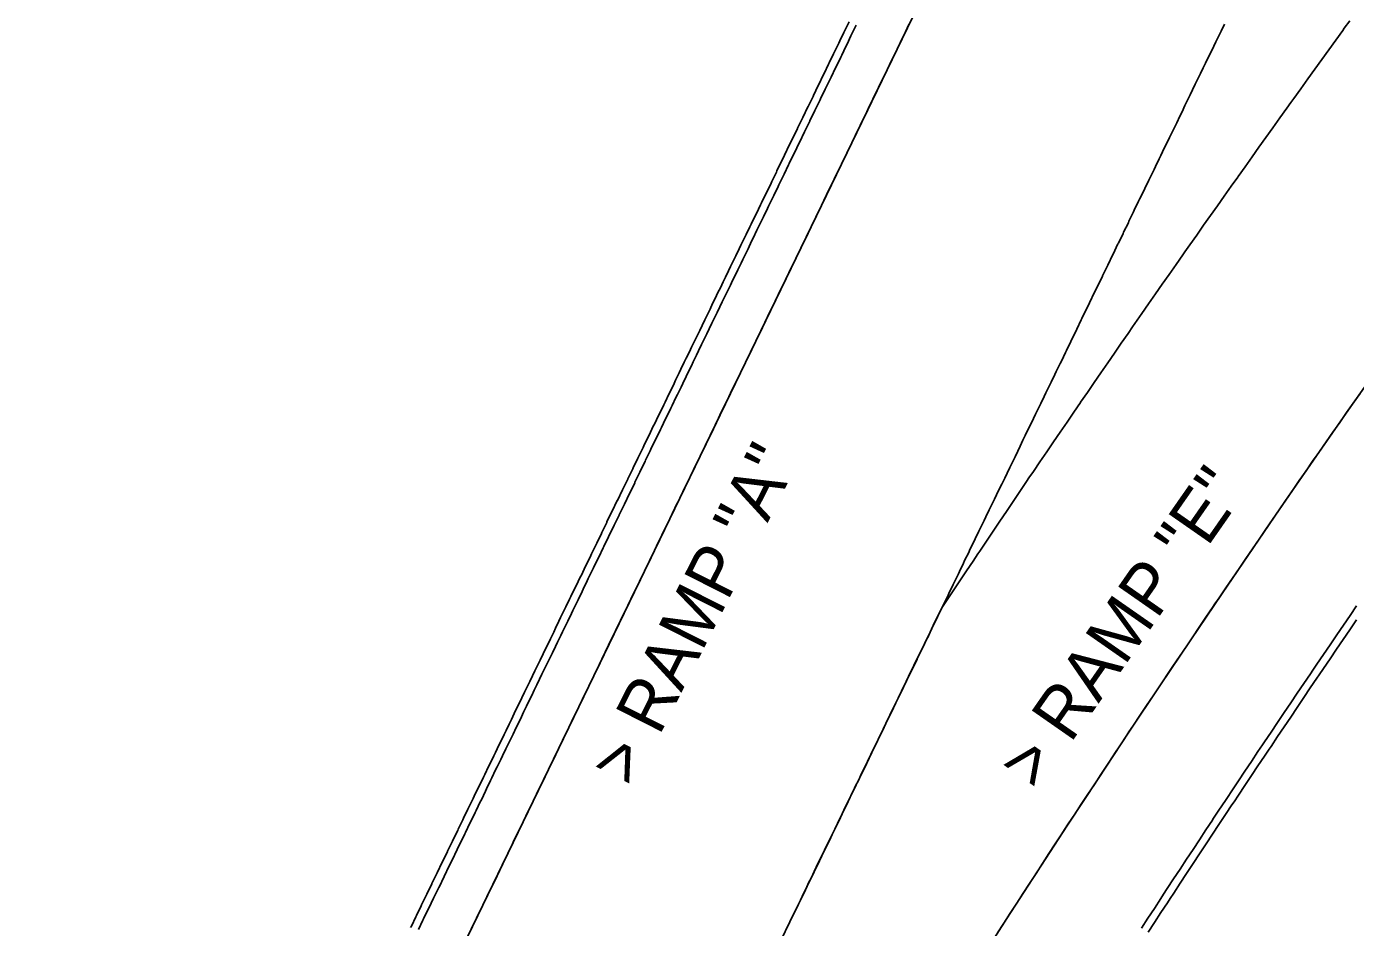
# Model space of a CAD drawing. Extents: x 2145147 to 2158018, y 137519 to 148068.
# Drawn here: x 2151102.2 to 2151214.6, y 141901.3 to 141977.5 of the extents above; entities that cross this region are included whole.
import ezdxf

# ---------------------------------------------------------------- set-up
doc = ezdxf.new("R2010")
doc.units = 0
for name, color, linetype in [('PR_Align_Ramp_A', 7, 'Continuous'), ('PR_Align_Ramp_A_Label', 7, 'Continuous'), ('PR_Align_Ramp_E', 7, 'Continuous'), ('PR_Align_Ramp_E_Label', 7, 'Continuous'), ('PR_Phasing_Pavement_1', 7, 'Continuous')]:
    doc.layers.add(name, color=color, linetype=linetype)

msp = doc.modelspace()

# ---------------------------------------------------------------- linework, layer by layer
at = {"layer": 'PR_Align_Ramp_A'}
msp.add_line((2151104.34, 141827.89), (2151311.03, 142254.91), dxfattribs=at)
at = {"layer": 'PR_Align_Ramp_E'}
msp.add_arc((2152388.44, 141125.03), 1432.39, 138.84043, 162.99163, dxfattribs=at)
at = {"layer": 'PR_Phasing_Pavement_1'}
for points in [[(2151134.68, 141901.28), (2151134.74, 141901.41), (2151135.12, 141902.21), (2151135.17, 141902.31), (2151135.57, 141903.13), (2151135.61, 141903.21), (2151136.02, 141904.06), (2151136.04, 141904.11), (2151136.47, 141904.98), (2151136.48, 141905.01), (2151136.92, 141905.91), (2151136.92, 141905.91), (2151137.35, 141906.81), (2151137.37, 141906.84), (2151137.79, 141907.71), (2151137.81, 141907.76), (2151138.22, 141908.61), (2151138.26, 141908.69), (2151138.66, 141909.51), (2151138.71, 141909.62), (2151139.1, 141910.41), (2151139.16, 141910.54), (2151139.53, 141911.31), (2151139.61, 141911.47), (2151139.97, 141912.21), (2151140.06, 141912.4), (2151140.4, 141913.11), (2151140.51, 141913.32), (2151140.84, 141914.01), (2151140.95, 141914.25), (2151141.27, 141914.91), (2151141.4, 141915.17), (2151141.71, 141915.81), (2151141.85, 141916.1), (2151142.14, 141916.71), (2151142.3, 141917.03), (2151142.58, 141917.61), (2151142.75, 141917.95), (2151143.02, 141918.51), (2151143.2, 141918.88), (2151143.45, 141919.41), (2151143.64, 141919.81), (2151143.89, 141920.31), (2151144.09, 141920.73), (2151144.32, 141921.21), (2151144.54, 141921.66), (2151144.76, 141922.11), (2151144.99, 141922.59), (2151145.19, 141923.01), (2151145.44, 141923.51), (2151145.63, 141923.91), (2151145.89, 141924.44), (2151146.06, 141924.81), (2151146.33, 141925.36), (2151146.5, 141925.71), (2151146.78, 141926.29), (2151146.94, 141926.61), (2151147.23, 141927.22), (2151147.37, 141927.51), (2151147.68, 141928.14), (2151147.81, 141928.41), (2151148.13, 141929.07), (2151148.24, 141929.31), (2151148.58, 141930), (2151148.68, 141930.21), (2151149.02, 141930.92), (2151149.12, 141931.11), (2151149.47, 141931.85), (2151149.55, 141932.01), (2151149.92, 141932.77), (2151149.99, 141932.91), (2151150.37, 141933.7), (2151150.42, 141933.81), (2151150.82, 141934.63), (2151150.86, 141934.71), (2151151.27, 141935.55), (2151151.29, 141935.61), (2151151.71, 141936.48), (2151151.73, 141936.51), (2151152.16, 141937.41), (2151152.17, 141937.41), (2151152.6, 141938.31), (2151152.61, 141938.33), (2151153.04, 141939.21), (2151153.06, 141939.26), (2151153.47, 141940.11), (2151153.51, 141940.19), (2151153.91, 141941.01), (2151153.96, 141941.11), (2151154.34, 141941.91), (2151154.4, 141942.04), (2151154.78, 141942.81), (2151154.85, 141942.96), (2151155.21, 141943.71), (2151155.3, 141943.89), (2151155.65, 141944.61), (2151155.75, 141944.82), (2151156.09, 141945.51), (2151156.2, 141945.74), (2151156.52, 141946.41), (2151156.65, 141946.67), (2151156.96, 141947.31), (2151157.1, 141947.6), (2151157.39, 141948.21), (2151157.54, 141948.52), (2151157.83, 141949.11), (2151157.99, 141949.45), (2151158.26, 141950.01), (2151158.44, 141950.38), (2151158.7, 141950.91), (2151158.89, 141951.3), (2151159.14, 141951.81), (2151159.34, 141952.23), (2151159.57, 141952.71), (2151159.79, 141953.15), (2151160.01, 141953.61), (2151160.23, 141954.08), (2151160.44, 141954.51), (2151160.68, 141955.01), (2151160.88, 141955.41), (2151161.13, 141955.93), (2151161.31, 141956.31), (2151161.58, 141956.86), (2151161.75, 141957.21), (2151162.03, 141957.79), (2151162.19, 141958.11), (2151162.48, 141958.71), (2151162.62, 141959.01), (2151162.92, 141959.64), (2151163.06, 141959.91), (2151163.37, 141960.57), (2151163.49, 141960.81), (2151163.82, 141961.49), (2151163.93, 141961.71), (2151164.27, 141962.42), (2151164.36, 141962.61), (2151164.72, 141963.35), (2151164.8, 141963.51), (2151165.17, 141964.27), (2151165.23, 141964.41), (2151165.62, 141965.2), (2151165.67, 141965.31), (2151166.06, 141966.12), (2151166.11, 141966.21), (2151166.51, 141967.05), (2151166.54, 141967.11), (2151166.96, 141967.98), (2151166.98, 141968.01), (2151167.41, 141968.9), (2151167.41, 141968.91), (2151167.85, 141969.81), (2151167.86, 141969.83), (2151168.28, 141970.71), (2151168.3, 141970.76), (2151168.72, 141971.61), (2151168.75, 141971.68), (2151169.16, 141972.52), (2151169.2, 141972.61), (2151169.59, 141973.41), (2151169.65, 141973.54), (2151170.03, 141974.32), (2151170.1, 141974.46), (2151170.46, 141975.21), (2151170.55, 141975.39), (2151170.9, 141976.11), (2151170.99, 141976.31), (2151171.33, 141977.02), (2151171.44, 141977.24), (2151171.77, 141977.91)], [(2151166.16, 141900.52), (2151166.6, 141901.43), (2151167.04, 141902.35), (2151167.49, 141903.27), (2151167.93, 141904.18), (2151168.37, 141905.1), (2151168.44, 141905.24), (2151168.82, 141906.01), (2151169.26, 141906.93), (2151169.7, 141907.85), (2151170.15, 141908.76), (2151170.59, 141909.68), (2151171.04, 141910.6), (2151171.48, 141911.52), (2151171.83, 141912.25), (2151171.92, 141912.43), (2151172.37, 141913.35), (2151172.81, 141914.27), (2151173.26, 141915.19), (2151173.7, 141916.11), (2151174.15, 141917.02), (2151174.59, 141917.94), (2151175.03, 141918.86), (2151175.23, 141919.26), (2151175.48, 141919.78), (2151175.92, 141920.7), (2151176.37, 141921.62), (2151176.81, 141922.54), (2151177.26, 141923.46), (2151177.7, 141924.38), (2151178.15, 141925.3), (2151178.6, 141926.22), (2151178.63, 141926.29), (2151179.04, 141927.14), (2151179.49, 141928.06), (2151179.63, 141928.35), (2151180.01, 141928.93), (2151180.57, 141929.77), (2151181.13, 141930.61), (2151181.7, 141931.46), (2151182.26, 141932.3), (2151182.67, 141932.91), (2151182.82, 141933.14), (2151183.39, 141933.98), (2151183.95, 141934.82), (2151184.52, 141935.66), (2151185.08, 141936.5), (2151185.65, 141937.34), (2151186.22, 141938.18), (2151186.79, 141939.02), (2151186.99, 141939.33), (2151187.36, 141939.86), (2151187.92, 141940.7), (2151188.49, 141941.54), (2151189.06, 141942.37), (2151189.64, 141943.21), (2151190.21, 141944.05), (2151190.78, 141944.88), (2151191.35, 141945.72), (2151191.36, 141945.73), (2151191.93, 141946.56), (2151192.5, 141947.39), (2151193.07, 141948.23), (2151193.65, 141949.06), (2151194.22, 141949.89), (2151194.8, 141950.73), (2151195.38, 141951.56), (2151195.75, 141952.1), (2151195.95, 141952.39), (2151196.53, 141953.23), (2151197.11, 141954.06), (2151197.69, 141954.89), (2151198.27, 141955.72), (2151198.85, 141956.55), (2151199.43, 141957.38), (2151200.01, 141958.21), (2151200.18, 141958.45), (2151200.59, 141959.04), (2151201.18, 141959.87), (2151201.76, 141960.7), (2151202.34, 141961.53), (2151202.93, 141962.35), (2151203.51, 141963.18), (2151204.1, 141964.01), (2151204.65, 141964.78), (2151204.68, 141964.83), (2151205.27, 141965.66), (2151205.86, 141966.49), (2151206.44, 141967.31), (2151207.03, 141968.14), (2151207.62, 141968.96), (2151208.21, 141969.79), (2151208.8, 141970.61), (2151209.14, 141971.09), (2151209.39, 141971.43), (2151209.98, 141972.26), (2151210.58, 141973.08), (2151211.17, 141973.9), (2151211.76, 141974.72), (2151212.35, 141975.54), (2151212.95, 141976.36), (2151213.54, 141977.18), (2151213.67, 141977.37), (2151214.14, 141978)], [(2151135.34, 141901.12), (2151135.72, 141901.91), (2151135.77, 141902.02), (2151136.17, 141902.84), (2151136.21, 141902.92), (2151136.62, 141903.77), (2151136.65, 141903.82), (2151137.07, 141904.69), (2151137.08, 141904.72), (2151137.52, 141905.62), (2151137.52, 141905.62), (2151137.95, 141906.52), (2151137.97, 141906.55), (2151138.39, 141907.42), (2151138.42, 141907.47), (2151138.82, 141908.32), (2151138.86, 141908.4), (2151139.26, 141909.22), (2151139.31, 141909.33), (2151139.69, 141910.12), (2151139.76, 141910.25), (2151140.13, 141911.02), (2151140.21, 141911.18), (2151140.57, 141911.92), (2151140.66, 141912.1), (2151141, 141912.82), (2151141.11, 141913.03), (2151141.44, 141913.72), (2151141.55, 141913.96), (2151141.87, 141914.62), (2151142, 141914.88), (2151142.31, 141915.52), (2151142.45, 141915.81), (2151142.74, 141916.42), (2151142.9, 141916.74), (2151143.18, 141917.32), (2151143.35, 141917.66), (2151143.62, 141918.22), (2151143.8, 141918.59), (2151144.05, 141919.12), (2151144.24, 141919.52), (2151144.49, 141920.02), (2151144.69, 141920.44), (2151144.92, 141920.92), (2151145.14, 141921.37), (2151145.36, 141921.82), (2151145.59, 141922.3), (2151145.79, 141922.72), (2151146.04, 141923.22), (2151146.23, 141923.62), (2151146.49, 141924.15), (2151146.67, 141924.52), (2151146.93, 141925.07), (2151147.1, 141925.42), (2151147.38, 141926), (2151147.54, 141926.32), (2151147.83, 141926.93), (2151147.97, 141927.22), (2151148.28, 141927.85), (2151148.41, 141928.12), (2151148.73, 141928.78), (2151148.84, 141929.02), (2151149.18, 141929.71), (2151149.28, 141929.92), (2151149.62, 141930.63), (2151149.71, 141930.82), (2151150.07, 141931.56), (2151150.15, 141931.72), (2151150.52, 141932.48), (2151150.59, 141932.62), (2151150.97, 141933.41), (2151151.02, 141933.52), (2151151.42, 141934.34), (2151151.46, 141934.42), (2151151.87, 141935.26), (2151151.89, 141935.32), (2151152.31, 141936.19), (2151152.33, 141936.22), (2151152.76, 141937.12), (2151152.76, 141937.12), (2151153.2, 141938.02), (2151153.21, 141938.04), (2151153.64, 141938.92), (2151153.66, 141938.97), (2151154.07, 141939.82), (2151154.11, 141939.9), (2151154.51, 141940.72), (2151154.56, 141940.82), (2151154.94, 141941.62), (2151155, 141941.75), (2151155.38, 141942.52), (2151155.45, 141942.67), (2151155.81, 141943.42), (2151155.9, 141943.6), (2151156.25, 141944.32), (2151156.35, 141944.53), (2151156.69, 141945.22), (2151156.8, 141945.45), (2151157.12, 141946.12), (2151157.25, 141946.38), (2151157.56, 141947.02), (2151157.7, 141947.31), (2151157.99, 141947.92), (2151158.14, 141948.23), (2151158.43, 141948.82), (2151158.59, 141949.16), (2151158.86, 141949.72), (2151159.04, 141950.09), (2151159.3, 141950.62), (2151159.49, 141951.01), (2151159.74, 141951.52), (2151159.94, 141951.94), (2151160.17, 141952.42), (2151160.39, 141952.86), (2151160.61, 141953.32), (2151160.83, 141953.79), (2151161.04, 141954.22), (2151161.28, 141954.72), (2151161.48, 141955.12), (2151161.73, 141955.64), (2151161.91, 141956.02), (2151162.18, 141956.57), (2151162.35, 141956.92), (2151162.63, 141957.5), (2151162.78, 141957.82), (2151163.08, 141958.42), (2151163.22, 141958.72), (2151163.52, 141959.35), (2151163.66, 141959.62), (2151163.97, 141960.28), (2151164.09, 141960.52), (2151164.42, 141961.2), (2151164.53, 141961.42), (2151164.87, 141962.13), (2151164.96, 141962.32), (2151165.32, 141963.05), (2151165.4, 141963.22), (2151165.77, 141963.98), (2151165.83, 141964.12), (2151166.21, 141964.91), (2151166.27, 141965.02), (2151166.66, 141965.83), (2151166.71, 141965.92), (2151167.11, 141966.76), (2151167.14, 141966.82), (2151167.56, 141967.69), (2151167.58, 141967.72), (2151168.01, 141968.61), (2151168.01, 141968.62), (2151168.45, 141969.52), (2151168.46, 141969.54), (2151168.88, 141970.42), (2151168.9, 141970.46), (2151169.32, 141971.32), (2151169.35, 141971.39), (2151169.76, 141972.22), (2151169.8, 141972.32), (2151170.19, 141973.12), (2151170.25, 141973.24), (2151170.63, 141974.02), (2151170.7, 141974.17), (2151171.06, 141974.92), (2151171.15, 141975.1), (2151171.5, 141975.82), (2151171.6, 141976.02), (2151171.93, 141976.72), (2151172.04, 141976.95), (2151172.37, 141977.62)], [(2151139.81, 141901.17), (2151140.22, 141902.02), (2151140.25, 141902.07), (2151140.67, 141902.95), (2151140.68, 141902.97), (2151141.12, 141903.87), (2151141.12, 141903.88), (2151141.55, 141904.77), (2151141.57, 141904.8), (2151141.99, 141905.67), (2151142.02, 141905.73), (2151142.42, 141906.57), (2151142.46, 141906.66), (2151142.86, 141907.47), (2151142.91, 141907.58), (2151143.29, 141908.37), (2151143.36, 141908.51), (2151143.73, 141909.27), (2151143.81, 141909.44), (2151144.17, 141910.17), (2151144.26, 141910.36), (2151144.6, 141911.07), (2151144.71, 141911.29), (2151145.04, 141911.97), (2151145.15, 141912.21), (2151145.47, 141912.88), (2151145.6, 141913.14), (2151145.91, 141913.77), (2151146.05, 141914.07), (2151146.35, 141914.67), (2151146.5, 141914.99), (2151146.78, 141915.57), (2151146.95, 141915.92), (2151147.22, 141916.47), (2151147.4, 141916.85), (2151147.65, 141917.38), (2151147.85, 141917.77), (2151148.09, 141918.27), (2151148.29, 141918.7), (2151148.52, 141919.17), (2151148.74, 141919.63), (2151148.96, 141920.08), (2151149.19, 141920.55), (2151149.4, 141920.98), (2151149.64, 141921.48), (2151149.83, 141921.88), (2151150.09, 141922.4), (2151150.27, 141922.78), (2151150.53, 141923.33), (2151150.7, 141923.68), (2151150.98, 141924.26), (2151151.14, 141924.58), (2151151.43, 141925.18), (2151151.57, 141925.48), (2151151.88, 141926.11), (2151152.01, 141926.38), (2151152.33, 141927.04), (2151152.44, 141927.28), (2151152.78, 141927.96), (2151152.88, 141928.18), (2151153.22, 141928.89), (2151153.32, 141929.08), (2151153.67, 141929.82), (2151153.75, 141929.98), (2151154.12, 141930.74), (2151154.19, 141930.88), (2151154.57, 141931.67), (2151154.62, 141931.78), (2151155.02, 141932.6), (2151155.06, 141932.68), (2151155.47, 141933.52), (2151155.49, 141933.58), (2151155.92, 141934.45), (2151155.93, 141934.48), (2151156.36, 141935.37), (2151156.37, 141935.38), (2151156.8, 141936.28), (2151156.81, 141936.3), (2151157.24, 141937.18), (2151157.26, 141937.23), (2151157.67, 141938.08), (2151157.71, 141938.15), (2151158.11, 141938.98), (2151158.16, 141939.08), (2151158.54, 141939.88), (2151158.61, 141940.01), (2151158.98, 141940.78), (2151159.05, 141940.93), (2151159.42, 141941.68), (2151159.5, 141941.86), (2151159.85, 141942.58), (2151159.95, 141942.79), (2151160.29, 141943.48), (2151160.4, 141943.71), (2151160.72, 141944.38), (2151160.85, 141944.64), (2151161.16, 141945.28), (2151161.3, 141945.56), (2151161.59, 141946.18), (2151161.74, 141946.49), (2151162.03, 141947.08), (2151162.19, 141947.42), (2151162.46, 141947.98), (2151162.64, 141948.34), (2151162.9, 141948.88), (2151163.09, 141949.27), (2151163.34, 141949.78), (2151163.54, 141950.2), (2151163.77, 141950.68), (2151163.99, 141951.12), (2151164.21, 141951.58), (2151164.44, 141952.05), (2151164.64, 141952.48), (2151164.88, 141952.97), (2151165.08, 141953.38), (2151165.33, 141953.9), (2151165.51, 141954.28), (2151165.78, 141954.83), (2151165.95, 141955.18), (2151166.23, 141955.75), (2151166.39, 141956.08), (2151166.68, 141956.68), (2151166.82, 141956.98), (2151167.12, 141957.61), (2151167.26, 141957.88), (2151167.57, 141958.53), (2151167.69, 141958.78), (2151168.02, 141959.46), (2151168.13, 141959.68), (2151168.47, 141960.39), (2151168.56, 141960.58), (2151168.92, 141961.31), (2151169, 141961.48), (2151169.37, 141962.24), (2151169.44, 141962.38), (2151169.81, 141963.16), (2151169.87, 141963.28), (2151170.26, 141964.09), (2151170.31, 141964.18), (2151170.71, 141965.02), (2151170.74, 141965.08), (2151171.16, 141965.94), (2151171.18, 141965.98), (2151171.61, 141966.87), (2151171.61, 141966.88), (2151172.05, 141967.78), (2151172.06, 141967.8), (2151172.48, 141968.68), (2151172.5, 141968.72), (2151172.92, 141969.58), (2151172.95, 141969.65), (2151173.36, 141970.48), (2151173.4, 141970.57), (2151173.79, 141971.38), (2151173.85, 141971.5), (2151174.23, 141972.28), (2151174.3, 141972.43), (2151174.66, 141973.18), (2151174.75, 141973.35), (2151175.1, 141974.08), (2151175.2, 141974.28), (2151175.53, 141974.98), (2151175.64, 141975.21), (2151175.97, 141975.88), (2151176.09, 141976.13), (2151176.41, 141976.78), (2151176.54, 141977.06), (2151176.84, 141977.68)], [(2151166.31, 141900.83), (2151166.64, 141901.52), (2151166.76, 141901.76), (2151167.08, 141902.42), (2151167.21, 141902.69), (2151167.51, 141903.32), (2151167.65, 141903.61), (2151167.95, 141904.22), (2151168.1, 141904.54), (2151168.38, 141905.12), (2151168.55, 141905.46), (2151168.82, 141906.02), (2151169, 141906.39), (2151169.25, 141906.92), (2151169.45, 141907.32), (2151169.69, 141907.82), (2151169.9, 141908.24), (2151170.13, 141908.72), (2151170.34, 141909.17), (2151170.56, 141909.62), (2151170.79, 141910.1), (2151171, 141910.52), (2151171.24, 141911.02), (2151171.43, 141911.42), (2151171.69, 141911.95), (2151171.87, 141912.32), (2151172.14, 141912.88), (2151172.3, 141913.22), (2151172.59, 141913.8), (2151172.74, 141914.12), (2151173.03, 141914.73), (2151173.18, 141915.02), (2151173.48, 141915.65), (2151173.61, 141915.92), (2151173.93, 141916.58), (2151174.05, 141916.82), (2151174.38, 141917.51), (2151174.48, 141917.72), (2151174.83, 141918.43), (2151174.92, 141918.62), (2151175.28, 141919.36), (2151175.35, 141919.52), (2151175.72, 141920.29), (2151175.79, 141920.42), (2151176.17, 141921.21), (2151176.22, 141921.32), (2151176.62, 141922.14), (2151176.66, 141922.22), (2151177.07, 141923.07), (2151177.1, 141923.12), (2151177.52, 141923.99), (2151177.53, 141924.02), (2151177.97, 141924.92), (2151177.97, 141924.92), (2151178.4, 141925.82), (2151178.42, 141925.84), (2151178.84, 141926.72), (2151178.86, 141926.77), (2151179.27, 141927.62), (2151179.31, 141927.7), (2151179.71, 141928.52), (2151179.76, 141928.62), (2151180.15, 141929.42), (2151180.21, 141929.55), (2151180.58, 141930.32), (2151180.66, 141930.48), (2151181.02, 141931.22), (2151181.1, 141931.4), (2151181.45, 141932.12), (2151181.55, 141932.33), (2151181.89, 141933.02), (2151182, 141933.26), (2151182.32, 141933.92), (2151182.45, 141934.18), (2151182.76, 141934.82), (2151182.9, 141935.11), (2151183.2, 141935.72), (2151183.35, 141936.03), (2151183.63, 141936.62), (2151183.79, 141936.96), (2151184.07, 141937.52), (2151184.24, 141937.89), (2151184.5, 141938.42), (2151184.69, 141938.81), (2151184.94, 141939.32), (2151185.14, 141939.74), (2151185.37, 141940.22), (2151185.59, 141940.67), (2151185.81, 141941.12), (2151186.04, 141941.59), (2151186.25, 141942.02), (2151186.48, 141942.52), (2151186.68, 141942.92), (2151186.93, 141943.44), (2151187.12, 141943.82), (2151187.38, 141944.37), (2151187.55, 141944.72), (2151187.83, 141945.3), (2151187.99, 141945.62), (2151188.28, 141946.22), (2151188.42, 141946.52), (2151188.73, 141947.15), (2151188.86, 141947.42), (2151189.18, 141948.08), (2151189.29, 141948.32), (2151189.62, 141949), (2151189.73, 141949.22), (2151190.07, 141949.93), (2151190.17, 141950.12), (2151190.52, 141950.86), (2151190.6, 141951.02), (2151190.97, 141951.78), (2151191.04, 141951.92), (2151191.42, 141952.71), (2151191.47, 141952.82), (2151191.87, 141953.63), (2151191.91, 141953.72), (2151192.31, 141954.56), (2151192.35, 141954.62), (2151192.76, 141955.49), (2151192.78, 141955.52), (2151193.21, 141956.41), (2151193.22, 141956.42), (2151193.65, 141957.32), (2151193.66, 141957.34), (2151194.09, 141958.22), (2151194.11, 141958.27), (2151194.52, 141959.12), (2151194.56, 141959.19), (2151194.96, 141960.02), (2151195, 141960.12), (2151195.4, 141960.92), (2151195.45, 141961.05), (2151195.83, 141961.83), (2151195.9, 141961.97), (2151196.27, 141962.73), (2151196.35, 141962.9), (2151196.7, 141963.63), (2151196.8, 141963.82), (2151197.14, 141964.53), (2151197.25, 141964.75), (2151197.57, 141965.43), (2151197.69, 141965.68), (2151198.01, 141966.33), (2151198.14, 141966.6), (2151198.44, 141967.23), (2151198.59, 141967.53), (2151198.88, 141968.13), (2151199.04, 141968.46), (2151199.32, 141969.03), (2151199.49, 141969.38), (2151199.75, 141969.93), (2151199.94, 141970.31), (2151200.19, 141970.83), (2151200.38, 141971.24), (2151200.62, 141971.73), (2151200.83, 141972.16), (2151201.06, 141972.63), (2151201.28, 141973.09), (2151201.49, 141973.53), (2151201.73, 141974.02), (2151201.93, 141974.43), (2151202.18, 141974.94), (2151202.37, 141975.33), (2151202.63, 141975.87), (2151202.8, 141976.23), (2151203.07, 141976.79), (2151203.24, 141977.13), (2151203.52, 141977.72)], [(2151184.33, 141900.83), (2151184.87, 141901.67), (2151185.41, 141902.51), (2151185.84, 141903.18), (2151185.95, 141903.35), (2151186.5, 141904.19), (2151187.04, 141905.03), (2151187.59, 141905.87), (2151188.13, 141906.71), (2151188.68, 141907.55), (2151189.22, 141908.38), (2151189.77, 141909.22), (2151190.01, 141909.59), (2151190.32, 141910.06), (2151190.87, 141910.89), (2151191.42, 141911.73), (2151191.97, 141912.56), (2151192.52, 141913.4), (2151193.07, 141914.23), (2151193.62, 141915.07), (2151194.17, 141915.9), (2151194.21, 141915.97), (2151194.72, 141916.74), (2151195.28, 141917.57), (2151195.45, 141917.84), (2151195.83, 141918.4), (2151196.38, 141919.23), (2151196.94, 141920.07), (2151197.49, 141920.9), (2151198.05, 141921.73), (2151198.45, 141922.33), (2151198.61, 141922.56), (2151199.16, 141923.39), (2151199.72, 141924.22), (2151200.28, 141925.05), (2151200.84, 141925.88), (2151201.4, 141926.71), (2151201.96, 141927.54), (2151202.52, 141928.37), (2151202.72, 141928.67), (2151203.08, 141929.19), (2151203.64, 141930.02), (2151204.2, 141930.85), (2151204.77, 141931.67), (2151205.33, 141932.5), (2151205.89, 141933.33), (2151206.46, 141934.15), (2151207.02, 141934.98), (2151207.03, 141934.98), (2151207.59, 141935.8), (2151208.15, 141936.62), (2151208.72, 141937.45), (2151209.29, 141938.27), (2151209.86, 141939.1), (2151210.43, 141939.92), (2151210.99, 141940.74), (2151211.37, 141941.27), (2151211.56, 141941.56), (2151212.14, 141942.38), (2151212.71, 141943.2), (2151213.28, 141944.02), (2151213.85, 141944.85), (2151214.42, 141945.66), (2151215, 141946.48)], [(2151196.51, 141901.25), (2151197.05, 141902.08), (2151197.6, 141902.91), (2151198.14, 141903.75), (2151198.38, 141904.11), (2151198.68, 141904.58), (2151199.23, 141905.41), (2151199.77, 141906.24), (2151200.32, 141907.07), (2151200.87, 141907.9), (2151201.41, 141908.72), (2151201.96, 141909.55), (2151202.51, 141910.38), (2151202.55, 141910.45), (2151203.06, 141911.21), (2151203.61, 141912.04), (2151203.78, 141912.3), (2151204.16, 141912.86), (2151204.71, 141913.69), (2151205.26, 141914.52), (2151205.81, 141915.34), (2151206.36, 141916.17), (2151206.76, 141916.76), (2151206.91, 141916.99), (2151207.47, 141917.82), (2151208.02, 141918.64), (2151208.57, 141919.47), (2151209.13, 141920.29), (2151209.68, 141921.11), (2151210.24, 141921.93), (2151210.8, 141922.76), (2151211, 141923.06), (2151211.35, 141923.58), (2151211.91, 141924.4), (2151212.47, 141925.22), (2151213.03, 141926.04), (2151213.59, 141926.86), (2151214.15, 141927.68), (2151214.71, 141928.5)], [(2151197.07, 141900.89), (2151197.61, 141901.72), (2151198.15, 141902.55), (2151198.7, 141903.38), (2151198.94, 141903.74), (2151199.24, 141904.21), (2151199.79, 141905.04), (2151200.33, 141905.87), (2151200.88, 141906.7), (2151201.42, 141907.53), (2151201.97, 141908.36), (2151202.52, 141909.19), (2151203.06, 141910.01), (2151203.11, 141910.08), (2151203.61, 141910.84), (2151204.16, 141911.67), (2151204.34, 141911.93), (2151204.71, 141912.49), (2151205.26, 141913.32), (2151205.81, 141914.15), (2151206.36, 141914.97), (2151206.91, 141915.8), (2151207.31, 141916.39), (2151207.47, 141916.62), (2151208.02, 141917.45), (2151208.57, 141918.27), (2151209.13, 141919.09), (2151209.68, 141919.92), (2151210.24, 141920.74), (2151210.79, 141921.56), (2151211.35, 141922.38), (2151211.55, 141922.68), (2151211.91, 141923.2), (2151212.46, 141924.03), (2151213.02, 141924.85), (2151213.58, 141925.67), (2151214.14, 141926.49), (2151214.7, 141927.31)]]:
    msp.add_lwpolyline(points, dxfattribs=at)

# ---------------------------------------------------------------- texts
at = {"layer": 'PR_Align_Ramp_A_Label'}
msp.add_text('> RAMP "A"', height=4.3, rotation=63.1006, dxfattribs=at).set_placement((2151153.46, 141913.01))
at = {"layer": 'PR_Align_Ramp_E_Label'}
msp.add_text('> RAMP "E"', height=4.3, rotation=55.122, dxfattribs=at).set_placement((2151187.66, 141912.74))

doc.saveas('drawing.dxf')
